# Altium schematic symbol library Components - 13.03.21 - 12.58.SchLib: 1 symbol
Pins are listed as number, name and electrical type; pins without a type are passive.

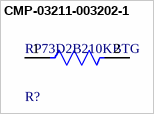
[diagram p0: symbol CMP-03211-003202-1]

## CMP-03211-003202-1
designator R?, comment RP73D2B210KBTG
Res Thin Film 1206 210KΩ 0.1% 0.25W 15ppm/°C Molded SMD; Manufacturer: TE Connectivity; Voltage Rating: 200V
footprint FP-RP732B-IPC_C
footprint FP-RP732B-IPC_A
footprint FP-RP732B-MFG
footprint FP-RP732B-IPC_B
pins: 1, 2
